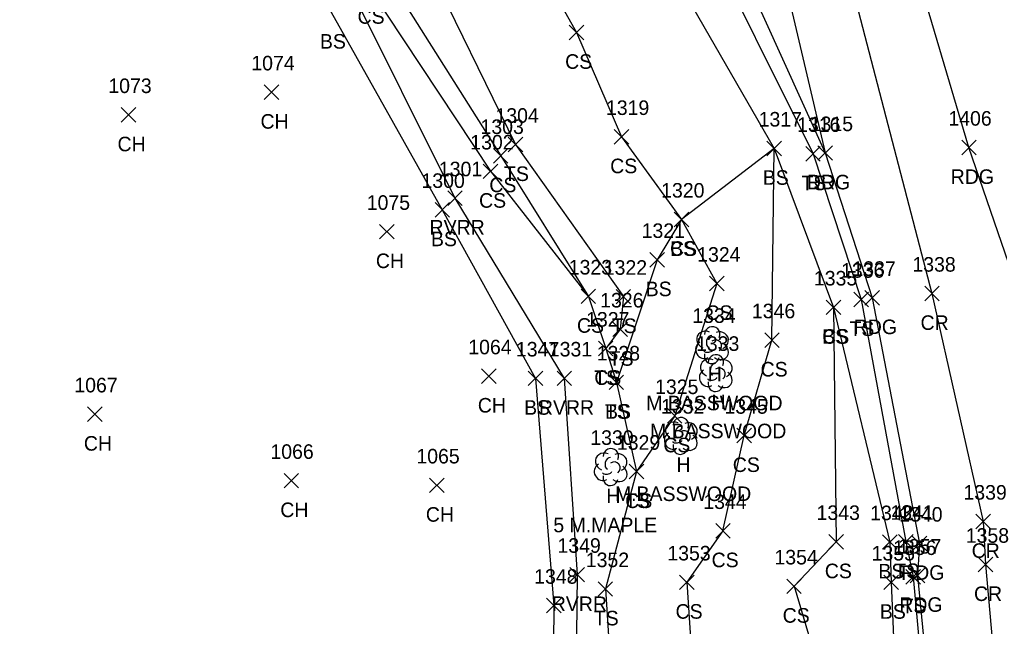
# Model space of a CAD drawing. Extents: x 1469310 to 1475157, y 493997 to 498873.
# Drawn here: x 1469498.4 to 1469633, y 498393.4 to 498476.8 of the extents above; entities that cross this region are included whole.
import ezdxf

# ---------------------------------------------------------------- set-up
doc = ezdxf.new("R2010")
doc.units = 0
for name, color, linetype in [('L_A', 7, 'Continuous'), ('L_C', 7, 'Continuous'), ('L_I', 7, 'Continuous'), ('L_TIC', 7, 'Continuous'), ('LAWE', 7, 'Continuous'), ('LELB', 7, 'Continuous'), ('LTD', 7, 'Continuous'), ('P_A', 7, 'Continuous'), ('P_I', 7, 'Continuous'), ('P_TIC', 7, 'Continuous'), ('PEU', 7, 'Continuous'), ('PRC', 7, 'Continuous'), ('R_A', 7, 'Continuous'), ('R_I', 7, 'Continuous'), ('R_TIC', 7, 'Continuous'), ('RDG', 7, 'Continuous')]:
    doc.layers.add(name, color=color, linetype=linetype)

msp = doc.modelspace()

# ---------------------------------------------------------------- linework, layer by layer
at = {"layer": 'L_TIC'}
for points in [[(1469573.86, 498474), (1469575.86, 498476)], [(1469575.86, 498474), (1469573.86, 498476)], [(1469531.98, 498465.78), (1469533.98, 498467.78)], [(1469533.98, 498465.78), (1469531.98, 498467.78)], [(1469512.34, 498462.67), (1469514.34, 498464.67)], [(1469514.34, 498462.67), (1469512.34, 498464.67)], [(1469580.06, 498459.66), (1469582.06, 498461.66)], [(1469582.06, 498459.66), (1469580.06, 498461.66)], [(1469565.51, 498458.59), (1469567.51, 498460.59)], [(1469567.51, 498458.59), (1469565.51, 498460.59)], [(1469565.51, 498458.59), (1469567.51, 498460.59)], [(1469567.51, 498458.59), (1469565.51, 498460.59)], [(1469563.46, 498457.05), (1469565.46, 498459.05)], [(1469565.46, 498457.05), (1469563.46, 498459.05)], [(1469601.02, 498458.07), (1469603.02, 498460.07)], [(1469603.02, 498458.07), (1469601.02, 498460.07)], [(1469601.02, 498458.07), (1469603.02, 498460.07)], [(1469603.02, 498458.07), (1469601.02, 498460.07)], [(1469606.36, 498457.33), (1469608.36, 498459.33)], [(1469608.36, 498457.33), (1469606.36, 498459.33)], [(1469562.05, 498454.92), (1469564.05, 498456.92)], [(1469564.05, 498454.92), (1469562.05, 498456.92)], [(1469557.18, 498451.24), (1469559.18, 498453.24)], [(1469559.18, 498451.24), (1469557.18, 498453.24)], [(1469555.44, 498449.64), (1469557.44, 498451.64)], [(1469557.44, 498449.64), (1469555.44, 498451.64)], [(1469588.28, 498448.31), (1469590.28, 498450.31)], [(1469590.28, 498448.31), (1469588.28, 498450.31)], [(1469588.28, 498448.31), (1469590.28, 498450.31)], [(1469590.28, 498448.31), (1469588.28, 498450.31)], [(1469547.83, 498446.63), (1469549.83, 498448.63)], [(1469549.83, 498446.63), (1469547.83, 498448.63)], [(1469584.94, 498442.77), (1469586.94, 498444.77)], [(1469586.94, 498442.77), (1469584.94, 498444.77)], [(1469593.14, 498439.51), (1469595.14, 498441.51)], [(1469595.14, 498439.51), (1469593.14, 498441.51)], [(1469575.5, 498437.75), (1469577.5, 498439.75)], [(1469577.5, 498437.75), (1469575.5, 498439.75)], [(1469575.5, 498437.75), (1469577.5, 498439.75)], [(1469577.5, 498437.75), (1469575.5, 498439.75)], [(1469580.31, 498437.71), (1469582.31, 498439.71)], [(1469582.31, 498437.71), (1469580.31, 498439.71)], [(1469612.96, 498437.31), (1469614.96, 498439.31)], [(1469614.96, 498437.31), (1469612.96, 498439.31)], [(1469609.17, 498436.24), (1469611.17, 498438.24)], [(1469611.17, 498436.24), (1469609.17, 498438.24)], [(1469609.17, 498436.24), (1469611.17, 498438.24)], [(1469611.17, 498436.24), (1469609.17, 498438.24)], [(1469579.88, 498433.22), (1469581.88, 498435.22)], [(1469581.88, 498433.22), (1469579.88, 498435.22)], [(1469600.72, 498431.74), (1469602.72, 498433.74)], [(1469602.72, 498431.74), (1469600.72, 498433.74)], [(1469577.88, 498430.59), (1469579.88, 498432.59)], [(1469579.88, 498430.59), (1469577.88, 498432.59)], [(1469577.88, 498430.59), (1469579.88, 498432.59)], [(1469579.88, 498430.59), (1469577.88, 498432.59)], [(1469561.83, 498426.79), (1469563.83, 498428.79)], [(1469563.83, 498426.79), (1469561.83, 498428.79)], [(1469568.24, 498426.49), (1469570.24, 498428.49)], [(1469570.24, 498426.49), (1469568.24, 498428.49)], [(1469572.2, 498426.49), (1469574.2, 498428.49)], [(1469574.2, 498426.49), (1469572.2, 498428.49)], [(1469579.35, 498425.94), (1469581.35, 498427.94)], [(1469581.35, 498425.94), (1469579.35, 498427.94)], [(1469579.35, 498425.94), (1469581.35, 498427.94)], [(1469581.35, 498425.94), (1469579.35, 498427.94)], [(1469507.72, 498421.56), (1469509.72, 498423.56)], [(1469509.72, 498421.56), (1469507.72, 498423.56)], [(1469587.36, 498421.33), (1469589.36, 498423.33)], [(1469589.36, 498421.33), (1469587.36, 498423.33)], [(1469596.89, 498418.63), (1469598.89, 498420.63)], [(1469598.89, 498418.63), (1469596.89, 498420.63)], [(1469582.12, 498413.68), (1469584.12, 498415.68)], [(1469584.12, 498413.68), (1469582.12, 498415.68)], [(1469582.12, 498413.68), (1469584.12, 498415.68)], [(1469584.12, 498413.68), (1469582.12, 498415.68)], [(1469534.7, 498412.43), (1469536.7, 498414.43)], [(1469536.7, 498412.43), (1469534.7, 498414.43)], [(1469554.69, 498411.8), (1469556.69, 498413.8)], [(1469556.69, 498411.8), (1469554.69, 498413.8)], [(1469593.99, 498405.55), (1469595.99, 498407.55)], [(1469595.99, 498405.55), (1469593.99, 498407.55)], [(1469593.99, 498405.55), (1469595.99, 498407.55)], [(1469595.99, 498405.55), (1469593.99, 498407.55)], [(1469609.54, 498404.04), (1469611.54, 498406.04)], [(1469611.54, 498404.04), (1469609.54, 498406.04)], [(1469616.9, 498404.01), (1469618.9, 498406.01)], [(1469618.9, 498404.01), (1469616.9, 498406.01)], [(1469619.12, 498404.06), (1469621.12, 498406.06)], [(1469621.12, 498404.06), (1469619.12, 498406.06)], [(1469573.96, 498399.53), (1469575.96, 498401.53)], [(1469575.96, 498399.53), (1469573.96, 498401.53)], [(1469620.11, 498399.23), (1469622.11, 498401.23)], [(1469622.11, 498399.23), (1469620.11, 498401.23)], [(1469577.84, 498397.56), (1469579.84, 498399.56)], [(1469579.84, 498397.56), (1469577.84, 498399.56)], [(1469589.04, 498398.48), (1469591.04, 498400.48)], [(1469591.04, 498398.48), (1469589.04, 498400.48)], [(1469603.75, 498397.93), (1469605.75, 498399.93)], [(1469605.75, 498397.93), (1469603.75, 498399.93)], [(1469617.1, 498398.47), (1469619.1, 498400.47)], [(1469619.1, 498398.47), (1469617.1, 498400.47)], [(1469570.75, 498395.28), (1469572.75, 498397.28)], [(1469572.75, 498395.28), (1469570.75, 498397.28)]]:
    msp.add_lwpolyline(points, dxfattribs=at)
at = {"layer": 'LAWE'}
msp.add_lwpolyline([(1469541.73, 498555.03), (1469545.19, 498552.67), (1469541.67, 498546.71), (1469525.68, 498530.28), (1469522.4, 498516.01), (1469543.45, 498481.78), (1469558.18, 498452.24), (1469573.2, 498427.49), (1469574.96, 498400.53), (1469574.71, 498375.54), (1469575.48, 498352.31), (1469575.94, 498330.63)], dxfattribs=at)
at = {"layer": 'LELB'}
for points in [[(1469416.82, 498734.31), (1469446.33, 498703.1), (1469470.89, 498677.65), (1469509.28, 498636.71), (1469524.42, 498615.8), (1469544.37, 498592.02), (1469564.88, 498563.16), (1469574.6, 498542.86), (1469576.57, 498532.67), (1469562.98, 498525.95), (1469548.2, 498517.37), (1469540.61, 498511.22), (1469554.07, 498484.99), (1469566.51, 498459.59)], [(1469428.53, 498658.9), (1469433.57, 498648.51), (1469459.29, 498614.44), (1469478.33, 498589.06), (1469483.97, 498576.63), (1469489.34, 498572.76), (1469492.49, 498571.98), (1469507.99, 498581.09), (1469520.42, 498585.29), (1469534.63, 498584.29), (1469538.32, 498574.02), (1469547.83, 498560.42), (1469557.44, 498552.67), (1469555.67, 498535.67), (1469539.85, 498524.73), (1469536.79, 498513.03), (1469549.04, 498482.48), (1469564.46, 498458.05), (1469576.5, 498438.75), (1469578.88, 498431.59)], [(1469542.74, 498553.27), (1469541.61, 498548.4), (1469522.4, 498532.22), (1469522.16, 498514.95), (1469541.19, 498477.77), (1469556.44, 498450.64), (1469569.24, 498427.49), (1469571.75, 498396.28), (1469571.57, 498374.72), (1469573.65, 498352.84), (1469573.82, 498331.47)], [(1469550.24, 498543.93), (1469544.51, 498542.94), (1469527.97, 498530.46), (1469525.18, 498518.63), (1469546.36, 498481.19), (1469563.05, 498455.92), (1469576.5, 498438.75)], [(1469557.7, 498505.6), (1469574.86, 498475), (1469581.06, 498460.66), (1469589.28, 498449.31), (1469594.14, 498440.51), (1469588.36, 498422.33), (1469583.12, 498414.68)], [(1469583.84, 498494.95), (1469584.94, 498488.74), (1469602.02, 498459.07), (1469610.17, 498437.24), (1469617.9, 498405.01), (1469618.1, 498399.47), (1469619.65, 498362.97), (1469614.57, 498335.86)], [(1469591.51, 498490.22), (1469607.36, 498458.33), (1469613.96, 498438.31), (1469620.12, 498405.06), (1469621.11, 498400.23), (1469624.57, 498362.54), (1469624.83, 498333.54)], [(1469566.51, 498459.59), (1469581.31, 498438.71), (1469580.88, 498434.22), (1469578.88, 498431.59), (1469580.35, 498426.94), (1469583.12, 498414.68), (1469578.84, 498398.56), (1469580.09, 498379.19), (1469580.44, 498349.96), (1469583.87, 498329.43)], [(1469602.02, 498459.07), (1469589.28, 498449.31), (1469585.94, 498443.77), (1469580.35, 498426.94)], [(1469601.72, 498432.74), (1469602.02, 498459.07)], [(1469610.17, 498437.24), (1469610.54, 498405.04), (1469604.75, 498398.93), (1469610.46, 498379.82)], [(1469594.99, 498406.55), (1469597.89, 498419.63), (1469601.72, 498432.74)], [(1469594.99, 498406.55), (1469590.04, 498399.48), (1469591.18, 498382.07), (1469598.89, 498358.29), (1469592.43, 498331.23)]]:
    msp.add_lwpolyline(points, dxfattribs=at)
at = {"layer": 'LTD'}
for p, q in [((1469593.47, 498432.1), (1469593.47, 498432.1)), ((1469593.47, 498432.1), (1469593.47, 498432.1)), ((1469593.98, 498428.26), (1469593.98, 498428.26)), ((1469593.98, 498428.26), (1469593.98, 498428.26)), ((1469589.17, 498419.64), (1469589.17, 498419.64)), ((1469589.17, 498419.64), (1469589.17, 498419.64)), ((1469579.55, 498415.35), (1469579.55, 498415.35)), ((1469579.55, 498415.35), (1469579.55, 498415.35))]:
    msp.add_line(p, q, dxfattribs=at)
for centre in [(1469593.52, 498433.54), (1469594.03, 498429.69), (1469589.22, 498421.07), (1469579.59, 498416.79)]:
    msp.add_arc(centre, 1.05, 335.5272, 180.9563, dxfattribs=at)
for centre, major_axis, ratio, start_param, end_param in [((1469592.68, 498432.77), (1.21, -0.51), 0.895232, 1.570796, 4.712389), ((1469593.26, 498432.56), (-0.208, -0.792), 0.645439, 3.141593, 6.283185), ((1469594.51, 498432.69), (-1.14, -0.48), 0.949671, 1.570796, 4.712389), ((1469592.39, 498431.4), (0.58, -1.04), 0.959034, 3.141593, 6.283185), ((1469593.97, 498431.94), (-0.5, 0.667), 0.989748, 3.141593, 6.283185), ((1469594.47, 498431.27), (-1.09, 0.79), 0.841452, 1.570796, 4.712389), ((1469593.47, 498430.6), (0.26, 1.06), 0.942809, 1.570796, 4.712389), ((1469593.01, 498431.35), (-0.625, -0.083), 0.423636, 0, 3.141593), ((1469593.19, 498428.93), (1.21, -0.51), 0.895232, 1.570796, 4.712389), ((1469593.77, 498428.72), (-0.208, -0.792), 0.645439, 3.141593, 6.283185), ((1469595.02, 498428.84), (-1.14, -0.48), 0.949671, 1.570796, 4.712389), ((1469592.9, 498427.55), (0.58, -1.04), 0.959034, 3.141593, 6.283185), ((1469594.48, 498428.09), (-0.5, 0.667), 0.989748, 3.141593, 6.283185), ((1469594.98, 498427.43), (-1.09, 0.79), 0.841452, 1.570796, 4.712389), ((1469593.98, 498426.76), (0.26, 1.06), 0.942809, 1.570796, 4.712389), ((1469593.52, 498427.51), (-0.625, -0.083), 0.423636, 0, 3.141593), ((1469588.38, 498420.3), (1.21, -0.51), 0.895232, 1.570796, 4.712389), ((1469590.21, 498420.22), (-1.14, -0.48), 0.949671, 1.570796, 4.712389), ((1469588.09, 498418.93), (0.58, -1.04), 0.959034, 3.141593, 6.283185), ((1469588.96, 498420.1), (-0.208, -0.792), 0.645439, 3.141593, 6.283185), ((1469589.67, 498419.47), (-0.5, 0.667), 0.989748, 3.141593, 6.283185), ((1469590.17, 498418.8), (-1.09, 0.79), 0.841452, 1.570796, 4.712389), ((1469589.17, 498418.14), (0.26, 1.06), 0.942809, 1.570796, 4.712389), ((1469588.71, 498418.89), (-0.625, -0.083), 0.423636, 0, 3.141593), ((1469578.75, 498416.02), (1.21, -0.51), 0.895232, 1.570796, 4.712389), ((1469580.59, 498415.94), (-1.14, -0.48), 0.949671, 1.570796, 4.712389), ((1469578.46, 498414.65), (0.58, -1.04), 0.959034, 3.141593, 6.283185), ((1469579.34, 498415.81), (-0.208, -0.792), 0.645439, 3.141593, 6.283185), ((1469580.05, 498415.19), (-0.5, 0.667), 0.989748, 3.141593, 6.283185), ((1469579.09, 498414.6), (-0.625, -0.083), 0.423636, 0, 3.141593), ((1469580.55, 498414.52), (-1.09, 0.79), 0.841452, 1.570796, 4.712389), ((1469579.55, 498413.85), (0.26, 1.06), 0.942809, 1.570796, 4.712389)]:
    msp.add_ellipse(centre, major_axis=major_axis, ratio=ratio, start_param=start_param, end_param=end_param, dxfattribs=at)
at = {"layer": 'P_TIC'}
for points in [[(1469627.78, 498458.19), (1469629.78, 498460.19)], [(1469629.78, 498458.19), (1469627.78, 498460.19)], [(1469608.03, 498457.44), (1469610.03, 498459.44)], [(1469610.03, 498457.44), (1469608.03, 498459.44)], [(1469622.7, 498438.14), (1469624.7, 498440.14)], [(1469624.7, 498438.14), (1469622.7, 498440.14)], [(1469614.47, 498437.56), (1469616.47, 498439.56)], [(1469616.47, 498437.56), (1469614.47, 498439.56)], [(1469629.72, 498406.83), (1469631.72, 498408.83)], [(1469631.72, 498406.83), (1469629.72, 498408.83)], [(1469620.98, 498403.81), (1469622.98, 498405.81)], [(1469622.98, 498403.81), (1469620.98, 498405.81)], [(1469630.04, 498400.91), (1469632.04, 498402.91)], [(1469632.04, 498400.91), (1469630.04, 498402.91)], [(1469620.72, 498399.42), (1469622.72, 498401.42)], [(1469622.72, 498399.42), (1469620.72, 498401.42)]]:
    msp.add_lwpolyline(points, dxfattribs=at)
at = {"layer": 'PEU'}
for points in [[(1469418.16, 498735.54), (1469447.91, 498704.22), (1469471.83, 498679.03), (1469509.9, 498637.99), (1469529.4, 498614.8), (1469545.14, 498594.13), (1469565.65, 498563.08), (1469576.41, 498543.24), (1469581.13, 498534.68), (1469591.75, 498510.08), (1469602.71, 498485.38), (1469609.03, 498458.44), (1469615.47, 498438.56), (1469621.98, 498404.81), (1469621.72, 498400.42), (1469625.38, 498362.57), (1469626.2, 498333.72)], [(1469637.73, 498433.09), (1469628.78, 498459.19), (1469619.32, 498491.12), (1469611.93, 498509.33), (1469599.41, 498542.19)]]:
    msp.add_lwpolyline(points, dxfattribs=at)
at = {"layer": 'PRC'}
msp.add_lwpolyline([(1469423.49, 498741.59), (1469452.57, 498710.45), (1469477.96, 498685.46), (1469512.01, 498647.6), (1469532.7, 498623.32), (1469554.78, 498596.5), (1469570.66, 498571.79), (1469585.25, 498547.18), (1469603.31, 498509.95), (1469610.7, 498488.94), (1469623.7, 498439.14), (1469630.72, 498407.83), (1469631.04, 498401.91), (1469634.46, 498363.9), (1469634.52, 498333.31)], dxfattribs=at)
at = {"layer": 'R_TIC'}
for points in [[(1469608.03, 498457.44), (1469610.03, 498459.44)], [(1469610.03, 498457.44), (1469608.03, 498459.44)]]:
    msp.add_lwpolyline(points, dxfattribs=at)
at = {"layer": 'RDG'}
msp.add_lwpolyline([(1469581.13, 498534.68), (1469576.37, 498529.22), (1469565.42, 498523), (1469549.02, 498515.64), (1469557.7, 498505.6), (1469574.42, 498505.02), (1469583.84, 498494.95), (1469591.51, 498490.22), (1469597.53, 498483.83), (1469609.03, 498458.44)], dxfattribs=at)

# ---------------------------------------------------------------- texts
at = {"layer": 'L_A'}
for s, p in [('CS', (1469544.8, 498476.19)), ('BS', (1469539.63, 498472.77)), ('CS', (1469573.31, 498470)), ('CH', (1469531.47, 498461.78)), ('CH', (1469511.83, 498458.67)), ('CS', (1469579.5, 498455.66)), ('TS', (1469564.92, 498454.59)), ('TS', (1469564.92, 498454.59)), ('BS', (1469600.46, 498454.07)), ('BS', (1469600.46, 498454.07)), ('CS', (1469562.9, 498453.05)), ('TS', (1469605.77, 498453.33)), ('CS', (1469561.49, 498450.92)), ('RVRR', (1469554.69, 498447.24)), ('BS', (1469554.88, 498445.64)), ('CS', (1469587.72, 498444.31)), ('BS', (1469587.72, 498444.31)), ('CH', (1469547.32, 498442.63)), ('BS', (1469584.38, 498438.77)), ('CS', (1469592.59, 498435.51)), ('CS', (1469574.94, 498433.75)), ('CS', (1469574.94, 498433.75)), ('TS', (1469579.72, 498433.71)), ('TS', (1469612.37, 498433.31)), ('CS', (1469608.62, 498432.24)), ('BS', (1469608.62, 498432.24)), ('TS', (1469579.29, 498429.22)), ('CS', (1469600.16, 498427.74)), ('TS', (1469577.29, 498426.59)), ('CS', (1469577.32, 498426.59)), ('H', (1469592.9, 498427.1)), ('H', (1469593.42, 498423.26)), ('CH', (1469561.32, 498422.79)), ('BS', (1469567.68, 498422.49)), ('RVRR', (1469569.71, 498422.49)), ('TS', (1469578.76, 498421.94)), ('BS', (1469578.79, 498421.94)), ('CH', (1469507.21, 498417.56)), ('CS', (1469586.8, 498417.33)), ('H', (1469588.6, 498414.64)), ('CS', (1469596.34, 498414.63)), ('H', (1469578.98, 498410.35)), ('TS', (1469581.53, 498409.68)), ('CS', (1469581.56, 498409.68)), ('CH', (1469534.19, 498408.43)), ('CH', (1469554.18, 498407.8)), ('CS', (1469593.43, 498401.55)), ('CS', (1469593.43, 498401.55)), ('CS', (1469608.98, 498400.04)), ('BS', (1469616.34, 498400.01)), ('TS', (1469618.53, 498400.06)), ('RVRR', (1469571.48, 498395.53)), ('TS', (1469619.52, 498395.23)), ('TS', (1469577.25, 498393.56)), ('CS', (1469588.48, 498394.48)), ('CS', (1469603.19, 498393.93)), ('BS', (1469616.54, 498394.47))]:
    msp.add_text(s, height=2, dxfattribs=at).set_placement(p)
at = {"layer": 'L_C'}
for s, p in [('M.BASSWOOD', (1469584.45, 498423.1)), ('M.BASSWOOD', (1469584.97, 498419.26)), ('M.BASSWOOD', (1469580.15, 498410.64)), ('5 M.MAPLE', (1469571.69, 498406.35))]:
    msp.add_text(s, height=2, dxfattribs=at).set_placement(p)
at = {"layer": 'L_I'}
for s, p in [('1074', (1469530.21, 498469.78)), ('1073', (1469510.57, 498466.67)), ('1319', (1469578.92, 498463.66)), ('1304', (1469563.74, 498462.59)), ('1304', (1469563.74, 498462.59)), ('1303', (1469561.69, 498461.05)), ('1317', (1469599.89, 498462.07)), ('1317', (1469599.89, 498462.07)), ('1316', (1469605.18, 498461.33)), ('1302', (1469560.28, 498458.92)), ('1301', (1469555.97, 498455.24)), ('1300', (1469553.58, 498453.64)), ('1320', (1469586.5, 498452.31)), ('1320', (1469586.5, 498452.31)), ('1075', (1469546.06, 498450.63)), ('1321', (1469583.82, 498446.77)), ('1324', (1469591.45, 498443.51)), ('1323', (1469573.81, 498441.75)), ('1323', (1469573.81, 498441.75)), ('1322', (1469578.62, 498441.71)), ('1336', (1469611.21, 498441.31)), ('1335', (1469607.48, 498440.24)), ('1335', (1469607.48, 498440.24)), ('1326', (1469578.13, 498437.22)), ('1346', (1469598.97, 498435.74)), ('1327', (1469576.19, 498434.59)), ('1327', (1469576.19, 498434.59)), ('1334', (1469590.78, 498435.1)), ('1333', (1469591.29, 498431.26)), ('1064', (1469560.01, 498430.79)), ('1347', (1469566.55, 498430.49)), ('1331', (1469571.07, 498430.49)), ('1328', (1469577.65, 498429.94)), ('1328', (1469577.65, 498429.94)), ('1067', (1469505.9, 498425.56)), ('1325', (1469585.67, 498425.33)), ('1332', (1469586.48, 498422.64)), ('1345', (1469595.2, 498422.63)), ('1330', (1469576.77, 498418.35)), ('1066', (1469532.83, 498416.43)), ('1329', (1469580.42, 498417.68)), ('1329', (1469580.42, 498417.68)), ('1065', (1469552.88, 498415.8)), ('1344', (1469592.29, 498409.55)), ('1344', (1469592.29, 498409.55)), ('1343', (1469607.85, 498408.04)), ('1342', (1469615.21, 498408.01)), ('1341', (1469617.99, 498408.06)), ('1349', (1469572.26, 498403.53)), ('1356', (1469618.36, 498403.23)), ('1352', (1469576.15, 498401.56)), ('1353', (1469587.35, 498402.48)), ('1354', (1469602.06, 498401.93)), ('1355', (1469615.41, 498402.47)), ('1348', (1469569.06, 498399.28))]:
    msp.add_text(s, height=2, dxfattribs=at).set_placement(p)
at = {"layer": 'P_A'}
for s, p in [('RDG', (1469626.27, 498454.19)), ('RDG', (1469606.52, 498453.44)), ('CR', (1469622.13, 498434.14)), ('RDG', (1469612.95, 498433.56)), ('CR', (1469629.15, 498402.83)), ('RDG', (1469619.46, 498399.81)), ('CR', (1469629.47, 498396.91)), ('RDG', (1469619.21, 498395.42))]:
    msp.add_text(s, height=2, dxfattribs=at).set_placement(p)
at = {"layer": 'P_I'}
for s, p in [('1406', (1469625.95, 498462.19)), ('1315', (1469606.91, 498461.44)), ('1338', (1469621.01, 498442.14)), ('1337', (1469612.77, 498441.56)), ('1339', (1469628.02, 498410.83)), ('1340', (1469619.2, 498407.81)), ('1358', (1469628.34, 498404.91)), ('1357', (1469619.03, 498403.42))]:
    msp.add_text(s, height=2, dxfattribs=at).set_placement(p)
at = {"layer": 'R_A'}
msp.add_text('DRG', height=2, dxfattribs=at).set_placement((1469606.52, 498453.44))
at = {"layer": 'R_I'}
msp.add_text('1315', height=2, dxfattribs=at).set_placement((1469606.91, 498461.44))

doc.saveas('drawing.dxf')
